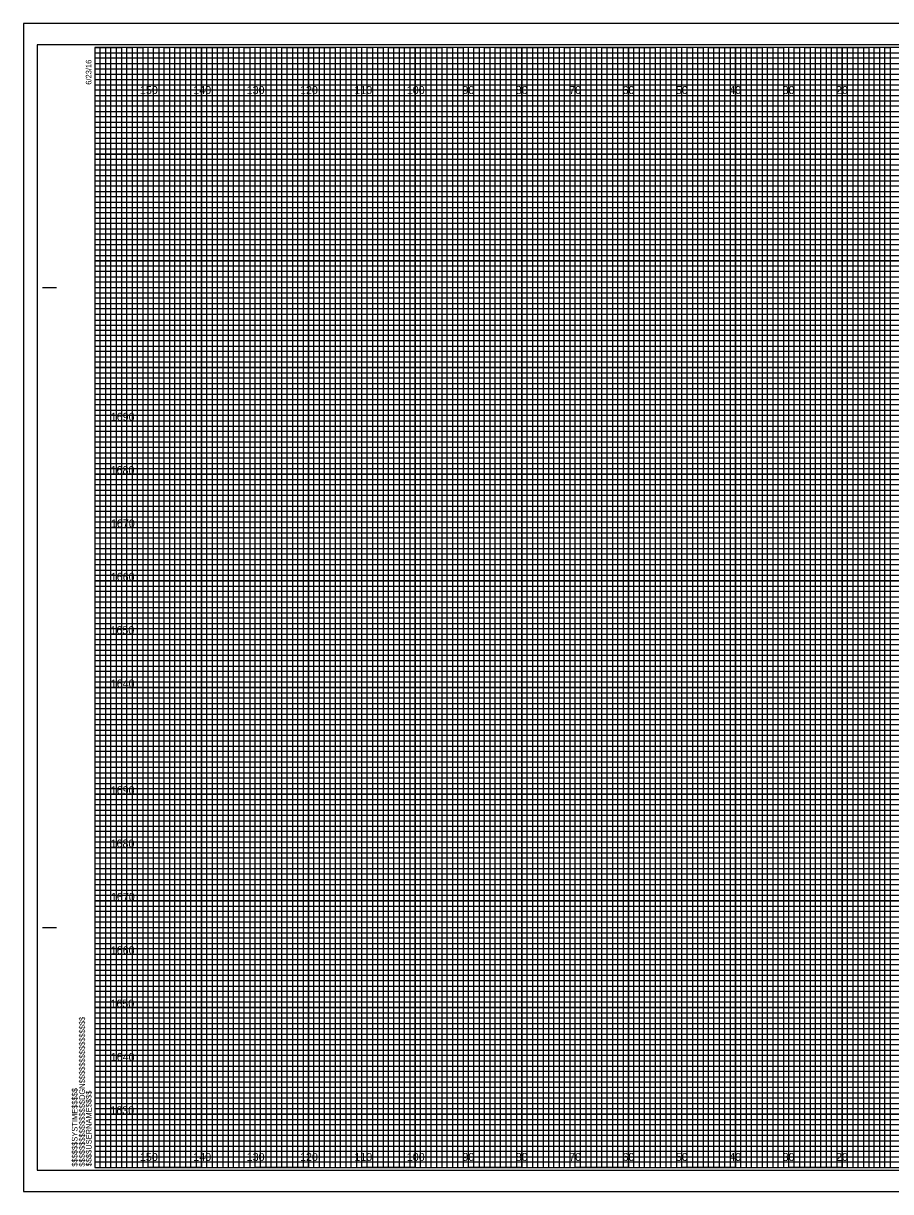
# Model space of a CAD drawing. Extents: x -419 to 4739, y -630 to 13534.
# Drawn here: x 2287.9 to 2450.4, y 415 to 634 of the extents above; entities that cross this region are included whole.
import ezdxf

# ---------------------------------------------------------------- set-up
doc = ezdxf.new("R2010")
doc.units = 0
for name, color, linetype in [('Old_Level_62', 7, 'Continuous'), ('Pattern 1', 7, 'Continuous'), ('Pattern 18', 7, 'Continuous'), ('Pattern 4', 7, 'Continuous'), ('Pattern 5', 7, 'Continuous'), ('Prop Dimension', 7, 'Continuous'), ('Prop Horizontal Alignment', 7, 'Continuous'), ('Raster_Level_0', 7, 'Continuous'), ('Scratch_Level_0', 7, 'Continuous'), ('Scratch_Level_3', 7, 'Continuous'), ('Scratch_Level_5', 7, 'Continuous')]:
    doc.layers.add(name, color=color, linetype=linetype)

msp = doc.modelspace()

# ---------------------------------------------------------------- linework, layer by layer
at = {"layer": 'Old_Level_62'}
for p, q in [((2291.53, 584.53), (2294.03, 584.53)), ((2291.63, 584.53), (2294.13, 584.53)), ((2291.53, 464.53), (2294.03, 464.53)), ((2291.63, 464.53), (2294.13, 464.53)), ((2301.33, 419.53), (2301.33, 419.53)), ((2301.33, 419.53), (2301.33, 419.53)), ((2301.33, 419.53), (2301.33, 419.53)), ((2301.33, 419.53), (2301.33, 419.53)), ((2301.33, 419.53), (2301.33, 419.53)), ((2301.33, 419.53), (2301.33, 419.53)), ((2301.33, 419.53), (2301.33, 419.53))]:
    msp.add_line(p, q, dxfattribs=at)
msp.add_lwpolyline([(2621.33, 629.53), (2301.33, 629.53), (2301.33, 419.53), (2621.33, 419.53)], close=True, dxfattribs=at)
at = {"layer": 'Pattern 18'}
msp.add_lwpolyline([(2287.93, 415.03), (2624.63, 415.03), (2624.63, 634.03), (2287.93, 634.03)], close=True, dxfattribs=at)
at = {"layer": 'Pattern 4'}
for p, q in [((2301.33, 628.53), (2561.33, 628.53)), ((2561.33, 627.51), (2301.33, 627.51)), ((2301.33, 627.51), (2301.33, 626.53)), ((2301.33, 626.53), (2561.33, 626.53)), ((2561.33, 625.42), (2301.33, 625.42)), ((2301.33, 625.42), (2301.33, 623.53)), ((2301.33, 623.53), (2621.33, 623.53))]:
    msp.add_line(p, q, dxfattribs=at)
for points in [[(2301.33, 622.53), (2571.33, 622.53), (2621.33, 622.53), (2621.33, 621.53), (2301.33, 621.53)], [(2301.33, 620.53), (2621.33, 620.53), (2621.33, 618.53), (2301.33, 618.53)], [(2301.33, 617.53), (2621.33, 617.53), (2621.33, 616.53), (2301.33, 616.51)], [(2301.33, 615.53), (2621.33, 615.53), (2621.33, 613.53), (2301.33, 613.53)], [(2301.33, 612.53), (2621.33, 612.53), (2621.33, 611.53), (2301.33, 611.53)], [(2301.33, 610.53), (2621.33, 610.53), (2621.33, 608.53), (2301.33, 608.53)], [(2301.33, 607.53), (2621.33, 607.53), (2621.33, 606.53), (2301.33, 606.53)], [(2301.33, 605.53), (2621.33, 605.53), (2621.33, 603.53), (2301.33, 603.53)], [(2301.33, 602.53), (2621.33, 602.53), (2621.33, 601.53), (2301.33, 601.53)], [(2301.33, 600.53), (2621.33, 600.53), (2621.33, 598.53), (2301.33, 598.53)], [(2301.33, 597.53), (2621.33, 597.53), (2621.33, 596.53), (2301.33, 596.53)], [(2301.33, 595.53), (2621.33, 595.53), (2621.33, 593.48), (2621.33, 592.53), (2621.33, 591.53), (2301.33, 591.53)], [(2301.33, 593.53), (2621.33, 593.53), (2621.33, 592.53), (2301.33, 592.53)], [(2301.33, 590.53), (2621.33, 590.53), (2621.33, 588.53), (2301.33, 588.56)], [(2301.33, 588.56), (2621.33, 588.53), (2621.33, 587.53), (2301.33, 587.53)], [(2301.33, 586.53), (2621.33, 586.53), (2621.33, 585.53), (2301.33, 585.53)], [(2301.33, 583.53), (2621.33, 583.53), (2621.33, 582.53), (2301.33, 582.53)], [(2301.33, 581.53), (2621.33, 581.53), (2621.33, 580.53), (2301.33, 580.53)], [(2301.26, 578.42), (2621.33, 578.42), (2621.33, 577.41), (2301.26, 577.41)], [(2301.33, 576.53), (2621.33, 576.53), (2621.33, 575.53), (2301.33, 575.53)], [(2301.33, 573.53), (2621.33, 573.53), (2621.33, 572.53), (2301.33, 572.53)], [(2301.33, 571.53), (2621.33, 571.53), (2621.33, 570.53), (2301.33, 570.53)], [(2301.33, 568.53), (2621.33, 568.53), (2621.33, 567.53), (2301.33, 567.53)], [(2301.33, 566.53), (2621.33, 566.53), (2621.33, 565.53), (2301.33, 565.53)], [(2301.33, 563.53), (2621.33, 563.53), (2621.33, 562.53), (2301.33, 562.53)], [(2301.33, 561.53), (2621.33, 561.53), (2621.33, 560.53), (2301.33, 560.53)], [(2301.33, 558.53), (2621.33, 558.53), (2621.32, 557.51), (2301.33, 557.53)], [(2301.33, 556.53), (2621.33, 556.53), (2621.33, 555.53), (2301.33, 555.53)], [(2301.33, 553.53), (2621.33, 553.53), (2621.33, 552.53), (2301.33, 552.53)], [(2301.33, 551.53), (2621.33, 551.53), (2621.33, 550.53), (2301.33, 550.53)], [(2301.33, 548.53), (2621.33, 548.53), (2621.33, 547.53), (2301.33, 547.53)], [(2301.33, 546.53), (2621.33, 546.53), (2621.33, 545.53), (2301.33, 545.53)], [(2301.33, 543.53), (2621.33, 543.53), (2621.33, 542.53), (2301.33, 542.53)], [(2301.33, 541.53), (2621.33, 541.53), (2621.33, 540.53), (2301.33, 540.53)], [(2301.33, 538.53), (2621.33, 538.53), (2621.33, 537.53), (2301.33, 537.53)], [(2301.33, 536.52), (2621.4, 536.44), (2621.33, 535.53), (2301.33, 535.53)], [(2301.33, 533.53), (2621.33, 533.53), (2621.33, 532.53), (2301.33, 532.53)], [(2301.33, 531.53), (2621.33, 531.53), (2621.33, 530.53), (2301.33, 530.53)], [(2301.33, 528.53), (2621.33, 528.53), (2621.33, 527.53), (2301.33, 527.53)], [(2301.33, 526.53), (2621.33, 526.53), (2621.33, 525.53), (2301.33, 525.53)], [(2301.33, 523.53), (2621.33, 523.53), (2621.33, 522.53), (2301.33, 522.53)], [(2301.33, 521.53), (2621.33, 521.53), (2621.33, 520.53), (2301.33, 520.53)], [(2301.33, 518.53), (2621.33, 518.53), (2621.33, 517.53), (2301.33, 517.53)], [(2301.33, 516.53), (2621.33, 516.53), (2621.33, 515.53), (2301.33, 515.53)], [(2301.33, 513.53), (2621.33, 513.53), (2621.33, 512.53), (2301.33, 512.53)], [(2301.33, 511.53), (2621.33, 511.53), (2621.33, 510.53), (2301.33, 510.53)], [(2301.33, 508.53), (2621.33, 508.53), (2621.33, 507.53), (2301.33, 507.53)], [(2301.33, 506.53), (2621.33, 506.53), (2621.33, 505.53), (2301.33, 505.53)], [(2301.33, 503.53), (2621.33, 503.53), (2621.33, 502.53), (2301.33, 502.53)], [(2301.33, 501.53), (2621.33, 501.53), (2621.33, 500.53), (2301.33, 500.53)], [(2301.33, 498.53), (2621.33, 498.53), (2621.32, 497.51), (2301.33, 497.53)], [(2301.33, 496.53), (2621.33, 496.53), (2621.33, 495.53), (2301.33, 495.53)], [(2301.33, 493.53), (2621.33, 493.53), (2621.33, 492.53), (2301.33, 492.53)], [(2301.33, 491.53), (2621.33, 491.53), (2621.33, 490.53), (2301.33, 490.53)], [(2301.33, 488.53), (2621.33, 488.53), (2621.33, 487.53), (2301.33, 487.53)], [(2301.33, 486.53), (2621.33, 486.53), (2621.33, 485.53), (2301.33, 485.53)], [(2301.33, 483.53), (2621.33, 483.53), (2621.33, 482.53), (2301.33, 482.53)], [(2301.33, 481.53), (2621.33, 481.53), (2621.33, 480.53), (2301.33, 480.53)], [(2301.33, 478.53), (2621.33, 478.53), (2621.33, 477.53), (2301.33, 477.53)], [(2301.33, 476.52), (2621.4, 476.44), (2621.33, 475.53), (2301.33, 475.53)], [(2301.33, 473.53), (2621.33, 473.53), (2621.33, 472.53), (2301.33, 472.53)], [(2301.33, 471.53), (2621.33, 471.53), (2621.33, 470.53), (2301.33, 470.53)], [(2301.33, 468.53), (2621.33, 468.53), (2621.33, 467.53), (2301.33, 467.53)], [(2301.33, 466.53), (2621.33, 466.53), (2621.33, 465.53), (2301.33, 465.53)], [(2301.33, 463.53), (2621.33, 463.53), (2621.33, 462.53), (2301.33, 462.53)], [(2301.33, 461.53), (2621.33, 461.53), (2621.33, 460.53), (2301.33, 460.53)], [(2301.33, 458.53), (2621.33, 458.53), (2621.33, 457.53), (2301.33, 457.53)], [(2301.33, 456.53), (2621.33, 456.53), (2621.33, 455.53), (2301.33, 455.53)], [(2301.33, 453.53), (2621.33, 453.53), (2621.33, 452.53), (2301.33, 452.53)], [(2301.33, 451.53), (2621.33, 451.53), (2621.33, 450.53), (2301.33, 450.53)], [(2301.33, 448.53), (2621.33, 448.53), (2621.33, 447.53), (2301.33, 447.53)], [(2301.33, 446.53), (2621.33, 446.53), (2621.33, 445.53), (2301.33, 445.53)], [(2301.33, 443.53), (2621.33, 443.53), (2621.33, 442.53), (2301.33, 442.53)], [(2301.33, 441.53), (2621.33, 441.53), (2621.33, 440.53), (2301.33, 440.53)], [(2301.33, 438.53), (2621.33, 438.53), (2621.33, 437.53), (2301.33, 437.53)], [(2301.33, 436.53), (2621.33, 436.53), (2621.33, 435.53), (2301.33, 435.53)], [(2301.33, 433.53), (2621.33, 433.53), (2621.33, 432.53), (2301.33, 432.53)], [(2301.33, 431.53), (2621.33, 431.53), (2621.33, 430.53), (2301.33, 430.53)], [(2301.33, 428.53), (2621.33, 428.53), (2621.33, 427.53), (2301.33, 427.53)], [(2301.33, 426.53), (2621.33, 426.53), (2621.33, 425.53), (2301.33, 425.53)], [(2301.33, 423.53), (2621.33, 423.53), (2621.33, 422.53), (2301.33, 422.53)], [(2301.33, 421.53), (2621.33, 421.53), (2621.33, 420.53), (2301.33, 420.53)]]:
    msp.add_lwpolyline(points, dxfattribs=at)
at = {"layer": 'Pattern 5'}
for p, q in [((2624.63, 634.03), (2287.93, 634.03)), ((2287.93, 634.03), (2287.93, 415.03)), ((2287.93, 415.03), (2624.63, 415.03))]:
    msp.add_line(p, q, dxfattribs=at)
at = {"layer": 'Prop Dimension'}
for points in [[(2301.33, 419.53), (2302.33, 419.53), (2302.33, 629.53), (2303.33, 629.53), (2303.33, 419.53)], [(2303.33, 419.53), (2304.33, 419.53), (2304.33, 629.53), (2305.33, 629.53), (2305.33, 419.53)], [(2306.33, 419.53), (2307.33, 419.53), (2307.33, 629.53), (2308.33, 629.53), (2308.33, 419.53)], [(2308.33, 419.53), (2309.33, 419.53), (2309.33, 629.53), (2310.33, 629.53), (2310.33, 419.53)], [(2311.33, 419.53), (2312.33, 419.53), (2312.33, 629.53), (2313.33, 629.53), (2313.33, 419.53)], [(2313.33, 419.53), (2314.33, 419.53), (2314.33, 629.53), (2315.33, 629.53), (2315.33, 419.53)], [(2316.33, 419.53), (2317.33, 419.53), (2317.33, 629.53), (2318.33, 629.53), (2318.33, 419.53)], [(2318.33, 419.53), (2319.33, 419.53), (2319.33, 629.53), (2320.33, 629.53), (2320.33, 419.53)], [(2321.33, 419.53), (2322.33, 419.53), (2322.33, 629.53), (2323.33, 629.53), (2323.33, 419.53)], [(2323.33, 419.53), (2324.33, 419.53), (2324.33, 629.53), (2325.33, 629.53), (2325.33, 419.53)], [(2326.33, 419.53), (2327.33, 419.53), (2327.33, 629.53), (2328.33, 629.53), (2328.33, 419.53)], [(2328.33, 419.53), (2329.33, 419.53), (2329.33, 629.53), (2330.33, 629.53), (2330.33, 419.53)], [(2331.33, 419.53), (2332.33, 419.53), (2332.33, 629.53), (2333.33, 629.53), (2333.33, 419.53)], [(2333.33, 419.53), (2334.33, 419.53), (2334.33, 629.53), (2335.33, 629.53), (2335.33, 419.53)], [(2336.33, 419.53), (2337.33, 419.53), (2337.33, 629.53), (2338.33, 629.53), (2338.33, 419.53)], [(2338.33, 419.53), (2339.33, 419.53), (2339.33, 629.53), (2340.33, 629.53), (2340.33, 419.53)], [(2341.33, 419.53), (2342.33, 419.53), (2342.33, 629.53), (2343.33, 629.53), (2343.33, 419.53)], [(2343.33, 419.53), (2344.33, 419.53), (2344.33, 629.53), (2345.33, 629.53), (2345.33, 419.53)], [(2346.33, 419.53), (2347.33, 419.53), (2347.33, 629.53), (2348.33, 629.53), (2348.33, 419.53)], [(2348.33, 419.53), (2349.33, 419.53), (2349.33, 629.53), (2350.33, 629.53), (2350.33, 419.53)], [(2351.33, 419.53), (2352.33, 419.53), (2352.33, 629.53), (2353.33, 629.53), (2353.33, 419.53)], [(2353.33, 419.53), (2354.33, 419.53), (2354.33, 629.53), (2355.33, 629.53), (2355.33, 419.53)], [(2356.33, 419.53), (2357.33, 419.53), (2357.33, 629.53), (2358.33, 629.53), (2358.33, 419.53)], [(2358.33, 419.53), (2359.33, 419.53), (2359.33, 629.53), (2360.33, 629.53), (2360.33, 419.53)], [(2361.33, 419.53), (2362.33, 419.53), (2362.33, 629.53), (2363.33, 629.53), (2363.33, 419.53)], [(2363.33, 419.53), (2364.33, 419.53), (2364.33, 629.53), (2365.33, 629.53), (2365.33, 419.53)], [(2366.33, 419.53), (2367.33, 419.53), (2367.33, 629.53), (2368.33, 629.53), (2368.33, 419.53)], [(2368.33, 419.53), (2369.33, 419.53), (2369.33, 629.53), (2370.33, 629.53), (2370.33, 419.53)], [(2371.33, 419.53), (2372.33, 419.53), (2372.33, 629.53), (2373.33, 629.53), (2373.33, 419.53)], [(2373.33, 419.53), (2374.33, 419.53), (2374.33, 629.53), (2375.33, 629.53), (2375.33, 419.53)], [(2376.33, 419.53), (2377.33, 419.53), (2377.33, 629.53), (2378.33, 629.53), (2378.33, 419.53)], [(2378.33, 419.53), (2379.33, 419.53), (2379.33, 629.53), (2380.33, 629.53), (2380.33, 419.53)], [(2381.33, 419.53), (2382.33, 419.53), (2382.33, 629.53), (2383.33, 629.53), (2383.33, 419.53)], [(2383.33, 419.53), (2384.33, 419.53), (2384.33, 629.53), (2385.33, 629.53), (2385.33, 419.53)], [(2386.33, 419.53), (2387.33, 419.53), (2387.33, 629.53), (2388.33, 629.53), (2388.33, 419.53)], [(2388.33, 419.53), (2389.33, 419.53), (2389.33, 629.53), (2390.33, 629.53), (2390.33, 419.53)], [(2391.33, 419.53), (2392.33, 419.53), (2392.33, 629.53), (2393.33, 629.53), (2393.33, 419.53)], [(2393.33, 419.53), (2394.33, 419.53), (2394.33, 629.53), (2395.33, 629.53), (2395.33, 419.53)], [(2396.33, 419.53), (2397.33, 419.53), (2397.33, 629.53), (2398.33, 629.53), (2398.33, 419.53)], [(2398.33, 419.53), (2399.33, 419.53), (2399.33, 629.53), (2400.33, 629.53), (2400.33, 419.53)], [(2401.33, 419.53), (2402.33, 419.53), (2402.33, 629.53), (2403.33, 629.53), (2403.33, 419.53)], [(2403.33, 419.53), (2404.33, 419.53), (2404.33, 629.53), (2405.33, 629.53), (2405.33, 419.53)], [(2406.33, 419.53), (2407.33, 419.53), (2407.33, 629.53), (2408.33, 629.53), (2408.33, 419.53)], [(2408.33, 419.53), (2409.33, 419.53), (2409.33, 629.53), (2410.33, 629.53), (2410.33, 419.53)], [(2411.33, 419.53), (2412.33, 419.53), (2412.33, 629.53), (2413.33, 629.53), (2413.33, 419.53)], [(2413.33, 419.53), (2414.33, 419.53), (2414.33, 629.53), (2415.33, 629.53), (2415.33, 419.53)], [(2416.33, 419.53), (2417.33, 419.53), (2417.33, 629.53), (2418.33, 629.53), (2418.33, 419.53)], [(2418.33, 419.53), (2419.33, 419.53), (2419.33, 629.53), (2420.33, 629.53), (2420.33, 419.53)], [(2421.33, 419.53), (2422.33, 419.53), (2422.33, 629.53), (2423.33, 629.53), (2423.33, 419.53)], [(2423.33, 419.53), (2424.33, 419.53), (2424.33, 629.53), (2425.33, 629.53), (2425.33, 419.53)], [(2426.33, 419.53), (2427.33, 419.53), (2427.33, 629.53), (2428.33, 629.53), (2428.33, 419.53)], [(2428.33, 419.53), (2429.33, 419.53), (2429.33, 629.53), (2430.33, 629.53), (2430.33, 419.53)], [(2431.33, 419.53), (2432.33, 419.53), (2432.33, 629.53), (2433.33, 629.53), (2433.33, 419.53)], [(2433.33, 419.53), (2434.33, 419.53), (2434.33, 629.53), (2435.33, 629.53), (2435.33, 419.53)], [(2436.33, 419.53), (2437.33, 419.53), (2437.33, 629.53), (2438.33, 629.53), (2438.33, 419.53)], [(2438.33, 419.53), (2439.33, 419.53), (2439.33, 629.53), (2440.33, 629.53), (2440.33, 419.53)], [(2441.33, 419.53), (2442.33, 419.53), (2442.33, 629.53), (2443.33, 629.53), (2443.33, 419.53)], [(2443.33, 419.53), (2444.33, 419.53), (2444.33, 629.53), (2445.33, 629.53), (2445.33, 419.53)], [(2446.33, 419.53), (2447.33, 419.53), (2447.33, 629.53), (2448.33, 629.53), (2448.33, 419.53)], [(2448.33, 419.53), (2449.33, 419.53), (2449.33, 629.53), (2450.33, 629.53), (2450.33, 419.53)]]:
    msp.add_lwpolyline(points, dxfattribs=at)
at = {"layer": 'Prop Horizontal Alignment'}
for points in [[(2301.33, 629.53), (2306.33, 629.53), (2306.33, 419.53), (2316.33, 419.53), (2316.33, 629.53), (2326.33, 629.53), (2326.33, 419.53), (2336.33, 419.53), (2336.33, 629.53), (2346.33, 629.53), (2346.33, 419.53), (2356.33, 419.53), (2356.33, 629.53), (2366.33, 629.53), (2366.33, 419.53), (2376.33, 419.53), (2376.33, 629.53), (2386.33, 629.53), (2386.33, 419.53), (2396.33, 419.53), (2396.33, 629.53), (2406.33, 629.53), (2406.33, 419.53), (2416.33, 419.53), (2416.33, 629.53), (2426.33, 629.53), (2426.33, 419.53), (2436.33, 419.53), (2436.33, 629.53), (2446.33, 629.53), (2446.33, 419.53), (2456.33, 419.53)], [(2301.33, 624.53), (2576.33, 624.53)], [(2301.33, 604.53), (2621.33, 604.53), (2621.33, 614.53), (2301.33, 614.53)], [(2301.33, 584.53), (2621.33, 584.53), (2621.33, 594.53), (2301.33, 594.53)], [(2301.33, 564.53), (2621.33, 564.53), (2621.33, 574.53), (2301.33, 574.53)], [(2301.33, 544.53), (2621.33, 544.53), (2621.33, 554.53), (2301.33, 554.53)], [(2301.33, 524.53), (2621.33, 524.53), (2621.33, 534.53), (2301.33, 534.53)], [(2301.33, 504.53), (2621.33, 504.53), (2621.33, 514.53), (2301.33, 514.53)], [(2301.33, 484.53), (2621.33, 484.53), (2621.33, 494.53), (2301.33, 494.53)], [(2301.33, 464.53), (2621.33, 464.53), (2621.33, 474.53), (2301.33, 474.53)], [(2301.33, 444.53), (2621.33, 444.53), (2621.33, 454.53), (2301.33, 454.53)], [(2301.33, 424.53), (2621.33, 424.53), (2621.33, 434.53), (2301.33, 434.53)]]:
    msp.add_lwpolyline(points, dxfattribs=at)
at = {"layer": 'Scratch_Level_0'}
for p, q in [((2311.33, 419.53), (2311.33, 629.53)), ((2321.33, 419.53), (2321.33, 629.53)), ((2331.33, 419.53), (2331.33, 629.53)), ((2341.33, 419.53), (2341.33, 629.53)), ((2351.33, 419.53), (2351.33, 629.53)), ((2361.33, 419.53), (2361.33, 629.53)), ((2371.33, 419.53), (2371.33, 629.53)), ((2381.33, 419.53), (2381.33, 629.53)), ((2391.33, 419.53), (2391.33, 629.53)), ((2401.33, 419.53), (2401.33, 629.53)), ((2411.33, 419.53), (2411.33, 629.53)), ((2421.33, 419.53), (2421.33, 629.53)), ((2431.33, 419.53), (2431.33, 629.53)), ((2441.33, 419.53), (2441.33, 629.53)), ((2301.33, 619.53), (2621.33, 619.53)), ((2301.33, 609.53), (2621.33, 609.53)), ((2301.33, 599.53), (2621.33, 599.53)), ((2301.33, 589.53), (2621.33, 589.53)), ((2301.33, 579.53), (2621.33, 579.53)), ((2301.33, 569.53), (2621.33, 569.53)), ((2301.33, 559.53), (2621.33, 559.53)), ((2301.33, 549.53), (2621.33, 549.53)), ((2301.33, 539.53), (2621.33, 539.53)), ((2301.33, 529.53), (2621.33, 529.53)), ((2301.33, 519.53), (2621.33, 519.53)), ((2301.33, 509.53), (2621.33, 509.53)), ((2301.33, 499.53), (2621.33, 499.53)), ((2301.33, 489.53), (2621.33, 489.53)), ((2301.33, 479.53), (2621.33, 479.53)), ((2301.33, 469.53), (2621.33, 469.53)), ((2301.33, 459.53), (2621.33, 459.53)), ((2301.33, 449.53), (2621.33, 449.53)), ((2301.33, 439.53), (2621.33, 439.53)), ((2301.33, 429.53), (2621.33, 429.53))]:
    msp.add_line(p, q, dxfattribs=at)
at = {"layer": 'Scratch_Level_3'}
for p, q in [((2311.33, 629.53), (2301.33, 629.53)), ((2311.33, 419.53), (2311.33, 629.53)), ((2331.33, 629.53), (2321.33, 629.53)), ((2321.33, 629.53), (2321.33, 419.53)), ((2331.33, 419.53), (2331.33, 629.53)), ((2351.33, 629.53), (2341.33, 629.53)), ((2341.33, 629.53), (2341.33, 419.53)), ((2351.33, 419.53), (2351.33, 629.53)), ((2371.33, 629.53), (2361.33, 629.53)), ((2361.33, 629.53), (2361.33, 419.53)), ((2371.33, 419.53), (2371.33, 629.53)), ((2391.33, 629.53), (2381.33, 629.53)), ((2381.33, 629.53), (2381.33, 419.53)), ((2391.33, 419.53), (2391.33, 629.53)), ((2411.33, 629.53), (2401.33, 629.53)), ((2401.33, 629.53), (2401.33, 419.53)), ((2411.33, 419.53), (2411.33, 629.53)), ((2431.33, 629.53), (2421.33, 629.53)), ((2421.33, 629.53), (2421.33, 419.53)), ((2431.33, 419.53), (2431.33, 629.53)), ((2451.33, 629.53), (2441.33, 629.53)), ((2441.33, 629.53), (2441.33, 419.53)), ((2321.33, 419.53), (2311.33, 419.53)), ((2341.33, 419.53), (2331.33, 419.53)), ((2361.33, 419.53), (2351.33, 419.53)), ((2381.33, 419.53), (2371.33, 419.53)), ((2401.33, 419.53), (2391.33, 419.53)), ((2421.33, 419.53), (2411.33, 419.53)), ((2441.33, 419.53), (2431.33, 419.53))]:
    msp.add_line(p, q, dxfattribs=at)
for points in [[(2301.33, 619.53), (2621.33, 619.53), (2621.33, 609.53), (2301.33, 609.53)], [(2301.33, 599.53), (2621.33, 599.53), (2621.33, 589.53), (2301.33, 589.53)], [(2301.33, 579.53), (2621.33, 579.53), (2621.33, 569.53), (2301.33, 569.53)], [(2301.33, 559.53), (2621.33, 559.53), (2621.33, 549.53), (2301.33, 549.53)], [(2301.33, 539.53), (2621.33, 539.53), (2621.33, 529.53), (2301.33, 529.53)], [(2301.33, 519.53), (2621.33, 519.53), (2621.33, 509.53), (2301.33, 509.53)], [(2301.33, 499.53), (2621.33, 499.53), (2621.33, 489.53), (2301.33, 489.53)], [(2301.33, 479.53), (2621.33, 479.53), (2621.33, 469.53), (2301.33, 469.53)], [(2301.33, 459.53), (2621.33, 459.53), (2621.33, 449.53), (2301.33, 449.53)], [(2301.33, 439.53), (2621.33, 439.53), (2621.33, 429.53), (2301.33, 429.53)]]:
    msp.add_lwpolyline(points, dxfattribs=at)
at = {"layer": 'Scratch_Level_5'}
msp.add_lwpolyline([(2290.53, 419.03), (2623.73, 419.03), (2623.73, 630.03), (2290.53, 630.03)], close=True, dxfattribs=at)

# ---------------------------------------------------------------- texts
at = {"layer": 'Old_Level_62'}
for s, p in [('6/23/16', (2300.68, 622.53)), ('$$$$$$$$$$$$$$$$DGN$$$$$$$$$$$$$$$$', (2299.45, 419.71)), ('$$$$$$SYSTIME$$$$$', (2298.07, 419.71)), ('$$$$USERNAME$$$$', (2300.71, 419.76))]:
    msp.add_text(s, height=1.05, rotation=90, dxfattribs=at).set_placement(p)
at = {"layer": 'Pattern 1'}
for s, p in [('1690', (2304.3, 559.53)), ('1680', (2304.27, 549.53)), ('1670', (2304.33, 539.53)), ('1660', (2304.3, 529.53)), ('1650', (2304.25, 519.53)), ('1640', (2304.3, 509.53)), ('1690', (2304.3, 489.53)), ('1680', (2304.27, 479.53)), ('1670', (2304.33, 469.53)), ('1660', (2304.3, 459.53)), ('1650', (2304.25, 449.53)), ('1640', (2304.3, 439.53)), ('1630', (2304.22, 429.53))]:
    msp.add_text(s, height=1.5, dxfattribs=at).set_placement(p)
at = {"layer": 'Raster_Level_0'}
for s, p in [('150', (2309.77, 620.78)), ('140', (2319.77, 620.78)), ('130', (2329.77, 620.78)), ('120', (2339.77, 620.78)), ('110', (2349.95, 620.78)), ('100', (2359.77, 620.78)), ('90', (2370.19, 620.78)), ('80', (2380.19, 620.78)), ('70', (2390.19, 620.78)), ('60', (2400.19, 620.78)), ('50', (2410.19, 620.78)), ('40', (2420.19, 620.78)), ('30', (2430.19, 620.78)), ('20', (2440.19, 620.78)), ('150', (2309.77, 420.78)), ('140', (2319.77, 420.78)), ('130', (2329.77, 420.78)), ('120', (2339.77, 420.78)), ('110', (2349.95, 420.78)), ('100', (2359.77, 420.78)), ('90', (2370.19, 420.78)), ('80', (2380.19, 420.78)), ('70', (2390.19, 420.78)), ('60', (2400.19, 420.78)), ('50', (2410.19, 420.78)), ('40', (2420.19, 420.78)), ('30', (2430.19, 420.78)), ('20', (2440.19, 420.78))]:
    msp.add_text(s, height=1.5, dxfattribs=at).set_placement(p)

doc.saveas('drawing.dxf')
